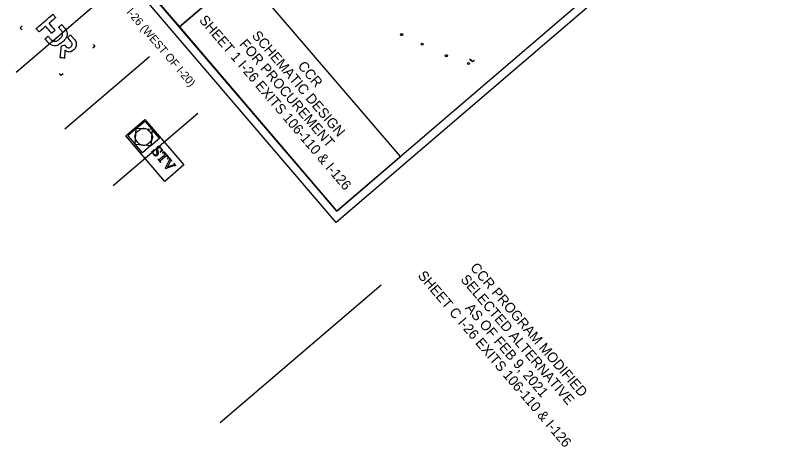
# Model space of a CAD drawing. Extents: x 1941897 to 1978064, y 805467 to 836604.
# Drawn here: x 1956688 to 1966166, y 805467 to 810856 of the extents above; entities that cross this region are included whole.
import ezdxf

# ---------------------------------------------------------------- set-up
doc = ezdxf.new("R2010")
doc.units = 0
for name, color, linetype in [('RD_EX_BldgApp', 7, 'Continuous'), ('RD_EX_BldgApp_TX', 7, 'Continuous'), ('RD_EX_DV_TX_Prop', 7, 'Continuous'), ('RD_EX_Misc', 7, 'Continuous'), ('RD_EX_RW_TxCode', 7, 'Continuous'), ('RD_EX_TX_RW_ELEV', 7, 'Continuous'), ('RD_EX_VEG', 7, 'Continuous'), ('RD_PD_Final_LnLine', 7, 'Continuous'), ('RD_SHT_Bndy', 7, 'Continuous'), ('RD_SHT_IplotShp', 7, 'Continuous'), ('RD_SHT_Misc2', 7, 'Continuous'), ('RD_SHT_Misc4', 7, 'Continuous'), ('RD_SHT_ShtClip', 7, 'Continuous'), ('RD_SHT_TX', 7, 'Continuous')]:
    doc.layers.add(name, color=color, linetype=linetype)

msp = doc.modelspace()

# ---------------------------------------------------------------- linework, layer by layer
at = {"layer": 'RD_EX_BldgApp'}
for p, q in [((1962402.7, 810274.8), (1962407.6, 810285.5)), ((1962409.9, 810284.2), (1962405.1, 810273.8))]:
    msp.add_line(p, q, dxfattribs=at)
for points in [[(1962404.9, 810275.2), (1962405.3, 810275.7), (1962405.4, 810276.2), (1962405.2, 810276.7), (1962404.8, 810277.1), (1962404.2, 810277.1), (1962403.7, 810276.9), (1962403.4, 810276.4), (1962403.4, 810275.8), (1962403.8, 810275.3), (1962404.3, 810275.1), (1962404.8, 810275.2), (1962404.9, 810275.2)], [(1962404.8, 810275.4), (1962405.2, 810275.8), (1962405.2, 810276.3), (1962404.9, 810276.7), (1962404.5, 810276.9), (1962404, 810276.8), (1962403.7, 810276.4), (1962403.6, 810275.9), (1962403.9, 810275.5), (1962404.3, 810275.3), (1962404.8, 810275.4)], [(1962404.7, 810275.6), (1962405, 810275.9), (1962405, 810276.4), (1962404.7, 810276.7), (1962404.2, 810276.7), (1962403.9, 810276.4), (1962403.8, 810276), (1962404, 810275.6), (1962404.4, 810275.5), (1962404.7, 810275.6)], [(1962404.6, 810275.8), (1962404.8, 810276.1), (1962404.7, 810276.4), (1962404.4, 810276.5), (1962404.1, 810276.4), (1962404, 810276), (1962404.2, 810275.7), (1962404.6, 810275.8), (1962404.6, 810275.8)], [(1962404.5, 810275.9), (1962404.6, 810276.2), (1962404.4, 810276.3), (1962404.2, 810276.2), (1962404.3, 810276), (1962404.5, 810275.9)], [(1962407.9, 810281.5), (1962408.3, 810281.9), (1962408.4, 810282.5), (1962408.2, 810283), (1962407.7, 810283.3), (1962407.2, 810283.4), (1962406.7, 810283.1), (1962406.4, 810282.6), (1962406.4, 810282.1), (1962406.7, 810281.6), (1962407.2, 810281.4), (1962407.8, 810281.5), (1962407.9, 810281.5)], [(1962407.8, 810281.7), (1962408.1, 810282.1), (1962408.2, 810282.6), (1962407.9, 810283), (1962407.4, 810283.2), (1962407, 810283.1), (1962406.6, 810282.7), (1962406.6, 810282.2), (1962406.8, 810281.8), (1962407.3, 810281.6), (1962407.8, 810281.7)], [(1962407.7, 810281.9), (1962407.9, 810282.2), (1962407.9, 810282.6), (1962407.6, 810282.9), (1962407.2, 810283), (1962406.8, 810282.7), (1962406.8, 810282.3), (1962407, 810281.9), (1962407.4, 810281.8), (1962407.7, 810281.9)], [(1962407.6, 810282), (1962407.8, 810282.3), (1962407.7, 810282.7), (1962407.3, 810282.8), (1962407, 810282.6), (1962407, 810282.3), (1962407.2, 810282), (1962407.5, 810282), (1962407.6, 810282)], [(1962407.5, 810282.2), (1962407.6, 810282.4), (1962407.4, 810282.6), (1962407.2, 810282.5), (1962407.2, 810282.2), (1962407.5, 810282.2)]]:
    msp.add_lwpolyline(points, dxfattribs=at)
at = {"layer": 'RD_EX_DV_TX_Prop'}
for centre, radius in [((1961516.9, 810613.9), 13.8), ((1961772.4, 810493.9), 13.7), ((1962075.3, 810349.3), 13.3), ((1962351.4, 810252.8), 13.7)]:
    msp.add_circle(centre, radius, dxfattribs=at)
at = {"layer": 'RD_EX_Misc'}
for p, q in [((1962422.9, 810289.4), (1962416.1, 810287.3)), ((1962420.5, 810285), (1962418.4, 810291.7)), ((1962418.4, 810291.7), (1962422.9, 810289.4))]:
    msp.add_line(p, q, dxfattribs=at)
for points in [[(1962367, 810300.8), (1962367.9, 810302.6), (1962366.1, 810303.5), (1962365.2, 810301.8), (1962367, 810300.8)], [(1962366.3, 810301.6), (1962366.1, 810301.7), (1962366, 810301.9), (1962366, 810302), (1962365.9, 810302.1), (1962365.9, 810302.3), (1962366, 810302.4), (1962366.1, 810302.6), (1962366.2, 810302.7), (1962366.3, 810302.7), (1962366.5, 810302.8), (1962366.6, 810302.8), (1962366.8, 810302.7), (1962366.8, 810302.7)], [(1962366.8, 810302.7), (1962366.9, 810302.6), (1962367, 810302.5), (1962367.1, 810302.4), (1962367.1, 810302.2), (1962367.1, 810302.1), (1962367.1, 810301.9), (1962367, 810301.8), (1962366.9, 810301.7), (1962366.7, 810301.6), (1962366.6, 810301.6), (1962366.4, 810301.6), (1962366.3, 810301.6), (1962366.3, 810301.6)], [(1962366.5, 810302.1), (1962366.4, 810302.1), (1962366.4, 810302.2), (1962366.5, 810302.3), (1962366.5, 810302.3), (1962366.6, 810302.3)], [(1962366.6, 810302.3), (1962366.6, 810302.2), (1962366.6, 810302.2), (1962366.6, 810302.1), (1962366.5, 810302.1), (1962366.5, 810302.1)], [(1962396.9, 810278.6), (1962397.8, 810280.4), (1962396, 810281.3), (1962395.1, 810279.6), (1962396.9, 810278.6)], [(1962396.2, 810279.4), (1962396, 810279.5), (1962395.9, 810279.7), (1962395.9, 810279.8), (1962395.8, 810279.9), (1962395.9, 810280.1), (1962395.9, 810280.2), (1962396, 810280.4), (1962396.1, 810280.5), (1962396.2, 810280.5), (1962396.4, 810280.6), (1962396.5, 810280.6), (1962396.7, 810280.5), (1962396.7, 810280.5)], [(1962396.7, 810280.5), (1962396.8, 810280.4), (1962396.9, 810280.3), (1962397, 810280.2), (1962397, 810280), (1962397, 810279.9), (1962397, 810279.7), (1962396.9, 810279.6), (1962396.8, 810279.5), (1962396.6, 810279.4), (1962396.5, 810279.4), (1962396.3, 810279.4), (1962396.2, 810279.4), (1962396.2, 810279.4)], [(1962396.4, 810279.9), (1962396.3, 810279.9), (1962396.3, 810280), (1962396.4, 810280.1), (1962396.4, 810280.1), (1962396.5, 810280.1)], [(1962396.5, 810280.1), (1962396.5, 810280), (1962396.5, 810280), (1962396.5, 810279.9), (1962396.5, 810279.9), (1962396.4, 810279.9)]]:
    msp.add_lwpolyline(points, dxfattribs=at)
msp.add_lwpolyline([(1962420.5, 810285), (1962416.1, 810287.3), (1962418.4, 810291.7), (1962422.9, 810289.4)], close=True, dxfattribs=at)
msp.add_circle((1962419.5, 810288.3), 0.15, dxfattribs=at)
at = {"layer": 'RD_EX_VEG'}
for centre in [(1962375.4, 810300.4), (1962382.5, 810293.9), (1962389.6, 810287.8)]:
    msp.add_circle(centre, 0.25, dxfattribs=at)
for centre, radius, start, end in [((1962373.7, 810300.5), 1.08, 97.42481, 267.20454), ((1962374.4, 810302.1), 0.995, 11.21113, 214.49527), ((1962374.8, 810298.9), 1.26, 158.90031, 357.18253), ((1962376.5, 810301.9), 1.22, 319.0152, 160.55315), ((1962377, 810299.9), 1.32, 229.33118, 68.20745), ((1962380.8, 810293.9), 1.08, 97.42481, 267.20454), ((1962381.5, 810295.6), 0.995, 11.21113, 214.49527), ((1962381.9, 810292.4), 1.26, 158.90031, 357.18253), ((1962383.6, 810295.4), 1.22, 319.0152, 160.55315), ((1962384, 810293.3), 1.32, 229.33118, 68.20745), ((1962387.9, 810287.9), 1.08, 97.42481, 267.20454), ((1962388.6, 810289.6), 0.995, 11.21113, 214.49527), ((1962389, 810286.4), 1.26, 158.90031, 357.18253), ((1962390.7, 810289.3), 1.22, 319.0152, 160.55315), ((1962391.2, 810287.3), 1.32, 229.33118, 68.20745)]:
    msp.add_arc(centre, radius, start, end, dxfattribs=at)
at = {"layer": 'RD_PD_Final_LnLine'}
msp.add_line((1961258.5, 807485.5), (1959248.4, 805764.6), dxfattribs=at)
at = {"layer": 'RD_SHT_Bndy'}
for points in [[(1960707.9, 808409.5), (1943668.8, 828312), (1948986.3, 832864.4), (1966025.3, 812961.9)], [(1957696.5, 811926.9), (1958739.3, 810708.9), (1959534.1, 811389.4), (1958491.3, 812607.4)], [(1958739.3, 810708.9), (1960707.9, 808409.5), (1961502.7, 809090), (1959534.1, 811389.4)]]:
    msp.add_lwpolyline(points, close=True, dxfattribs=at)
at = {"layer": 'RD_SHT_IplotShp'}
msp.add_lwpolyline([(1960696.9, 808268.5), (1943527.9, 828323), (1948997.3, 833005.4), (1966166.3, 812950.9)], close=True, dxfattribs=at)
at = {"layer": 'RD_SHT_Misc2'}
for points in [[(1956773.4, 810673.3), (1956751.4, 810699), (1956777, 810720.9)], [(1957662.8, 810489.7), (1957684.7, 810464.1), (1957659.1, 810442.1)], [(1957287.8, 810124.3), (1957262.2, 810102.3), (1957240.2, 810128)]]:
    msp.add_lwpolyline(points, dxfattribs=at)
for points in [[(1957186.8, 810665.7), (1957186.8, 810665.7), (1957111.7, 810753.5), (1957111.7, 810753.5), (1957111.7, 810753.5), (1957111.7, 810753.5), (1957195.1, 810824.9), (1957195.1, 810824.9), (1957195.1, 810824.9), (1957195.1, 810824.9), (1957158.9, 810867.1), (1957158.9, 810867.1), (1957158.9, 810867.1), (1957158.9, 810867.1), (1956950.4, 810688.6), (1956950.4, 810688.6), (1956950.4, 810688.6), (1956950.4, 810688.6), (1956986.6, 810646.3), (1956986.6, 810646.3), (1956986.6, 810646.3), (1956986.6, 810646.3), (1957070, 810717.8), (1957070, 810717.8), (1957070, 810717.8), (1957070, 810717.8), (1957145.1, 810630), (1957145.1, 810630), (1957145.1, 810630), (1957145.1, 810630), (1957186.8, 810665.7), (1957186.8, 810665.7)], [(1957275.5, 810520.1), (1957275.5, 810520.1), (1957275.6, 810520.2), (1957275.6, 810520.2), (1957275.6, 810520.2), (1957275.6, 810520.2), (1957275.6, 810520.2), (1957275.6, 810520.2), (1957275.6, 810520.2), (1957335.8, 810572), (1957342, 810653.2), (1957290.4, 810713.6), (1957290.4, 810713.6), (1957290.4, 810713.6), (1957269.3, 810738.2), (1957269.3, 810738.2), (1957269.3, 810738.2), (1957269.3, 810738.2), (1957230.1, 810704.7), (1957230.1, 810704.7), (1957230.1, 810704.7), (1957230.1, 810704.7), (1957251.2, 810680.1), (1957251.2, 810680.1), (1957251.2, 810680.1), (1957284, 810641.7), (1957280.2, 810592.1), (1957242, 810559.2), (1957242, 810559.2), (1957203.7, 810526.6), (1957153.8, 810530.2), (1957121, 810568.6), (1957121, 810568.6), (1957121, 810568.6), (1957099.9, 810593.2), (1957099.9, 810593.2), (1957099.9, 810593.2), (1957099.9, 810593.2), (1957060.7, 810559.7), (1957060.7, 810559.7), (1957060.7, 810559.7), (1957060.7, 810559.7), (1957081.8, 810535), (1957081.8, 810535), (1957081.8, 810535), (1957133.5, 810474.7), (1957215, 810468.5), (1957275.4, 810520), (1957275.4, 810520), (1957275.4, 810520), (1957275.4, 810520), (1957275.4, 810520), (1957275.4, 810520), (1957275.4, 810520), (1957275.5, 810520.1), (1957275.5, 810520.1)], [(1957342.1, 810577.2), (1957342.1, 810577.2), (1957382.4, 810530.1), (1957382.4, 810530.1), (1957382.4, 810530.1), (1957394.6, 810515.9), (1957399.8, 810503.8), (1957399, 810491), (1957399, 810491), (1957398.1, 810479.3), (1957392.8, 810469), (1957383.5, 810461.1), (1957383.5, 810461.1), (1957362.4, 810443.1), (1957334.3, 810450.5), (1957317, 810470.8), (1957317, 810470.8), (1957317, 810470.8), (1957306.9, 810482.5), (1957306.9, 810482.5), (1957306.9, 810482.5), (1957306.9, 810482.5), (1957265.3, 810470.8), (1957265.3, 810470.8), (1957265.3, 810470.8), (1957265.3, 810470.8), (1957251.4, 810325.4), (1957251.4, 810325.4), (1957251.4, 810325.4), (1957251.4, 810325.4), (1957302.2, 810317), (1957302.2, 810317), (1957302.2, 810317), (1957302.2, 810317), (1957310.5, 810418.8), (1957310.5, 810418.8), (1957310.5, 810418.8), (1957342, 810393.4), (1957387.1, 810396.4), (1957416.2, 810421.3), (1957416.2, 810421.3), (1957437.9, 810439.9), (1957449.4, 810460.4), (1957450.7, 810488.4), (1957450.7, 810488.4), (1957452.1, 810517.4), (1957440.4, 810538.3), (1957417.4, 810565.2), (1957417.4, 810565.2), (1957417.4, 810565.2), (1957379.6, 810609.3), (1957379.6, 810609.3), (1957379.6, 810609.3), (1957379.6, 810609.3), (1957342.1, 810577.2), (1957342.1, 810577.2)]]:
    msp.add_open_spline(points, degree=3, dxfattribs=at)
at = {"layer": 'RD_SHT_Misc4'}
for points in [[(1958308.3, 809555.4), (1958796.1, 808985.7), (1958557, 808781), (1958069.3, 809350.8)], [(1958532, 809173.5), (1958530.3, 809175.5), (1958524.2, 809173.3), (1958520.5, 809175.3), (1958517.7, 809182.4), (1958513.6, 809192.9), (1958508.1, 809201.4), (1958502.7, 809206.8), (1958497, 809210.7), (1958490.8, 809213.5), (1958484.1, 809214.9), (1958477.6, 809215.1), (1958471.4, 809214), (1958465.8, 809211.8), (1958460.7, 809208.2), (1958455.8, 809202.8), (1958452.6, 809196.6), (1958450.9, 809189.5), (1958450.7, 809181.5), (1958454.7, 809155.5), (1958458.5, 809133.6), (1958456.8, 809122.3), (1958451.3, 809114.4), (1958444.3, 809110.6), (1958436.1, 809109.9), (1958427.6, 809112.8), (1958420, 809119.3), (1958414.8, 809127.1), (1958411.8, 809135.6), (1958410.9, 809144.2), (1958412.2, 809151.9), (1958416.2, 809159.9), (1958423.2, 809169.5), (1958421.5, 809171.4), (1958391.2, 809145.3), (1958392.7, 809143.5), (1958398.6, 809146), (1958402, 809144.3), (1958406.7, 809133.9), (1958411.3, 809123), (1958417.2, 809115), (1958422.8, 809109.3), (1958428.8, 809105.2), (1958435.3, 809102.2), (1958442.3, 809100.8), (1958449.2, 809100.7), (1958455.6, 809101.8), (1958461.6, 809104.3), (1958467, 809108), (1958471.8, 809113.2), (1958475.3, 809119.4), (1958477.5, 809126.3), (1958478.1, 809133.7), (1958473.9, 809160.2), (1958470.7, 809179.7), (1958470.8, 809192.1), (1958472.6, 809197.4), (1958476.2, 809201.7), (1958482.5, 809205.1), (1958490.2, 809205.6), (1958497.9, 809203.2), (1958504.6, 809197.7), (1958509, 809190.9), (1958511.8, 809182.8), (1958512.4, 809174.4), (1958510.8, 809166.3), (1958506.7, 809158.2), (1958499.8, 809149.4), (1958501.5, 809147.5)], [(1958609.9, 809078.5), (1958548, 809150.9), (1958527, 809136.2), (1958529.2, 809133.7), (1958535.5, 809137.4), (1958541.4, 809139.2), (1958546.7, 809139.1), (1958551.2, 809137.6), (1958559.5, 809129.6), (1958568.5, 809119.1), (1958496.3, 809057.1), (1958489.7, 809052.2), (1958485.2, 809050.3), (1958479.7, 809051.4), (1958474.4, 809055.7), (1958471.6, 809059.1), (1958469.7, 809057.5), (1958503.9, 809017.5), (1958505.8, 809019.1), (1958503, 809022.4), (1958499.6, 809027.8), (1958498.8, 809032.9), (1958501.3, 809037.5), (1958507.7, 809043.9), (1958579.9, 809105.8), (1958591.2, 809092.8), (1958595, 809087.2), (1958597.2, 809082), (1958597.5, 809076.9), (1958596.2, 809071.5), (1958589.9, 809062.6), (1958592.2, 809060.1)], [(1958696.4, 808977.6), (1958672.7, 809005.2), (1958670.9, 809003.6), (1958671.6, 809002.3), (1958674, 808997.5), (1958674.7, 808993.5), (1958672.7, 808988.4), (1958659.2, 808982.4), (1958589.6, 808957.3), (1958622.4, 809026.7), (1958630.2, 809038.6), (1958632.7, 809040.1), (1958635.8, 809040.2), (1958639.6, 809038.4), (1958644.9, 809033.9), (1958646.8, 809035.5), (1958614.4, 809073.3), (1958612.5, 809071.6), (1958616.5, 809063.7), (1958616.5, 809056.6), (1958611.7, 809046.1), (1958563.4, 808944.1), (1958566.4, 808940.6), (1958668.6, 808977.3), (1958677.5, 808979.8), (1958684.8, 808980.3), (1958689.5, 808979), (1958694.5, 808975.9)]]:
    msp.add_lwpolyline(points, close=True, dxfattribs=at)
for points in [[(1958201, 809442), (1958307.7, 809533.3), (1958399.2, 809426.4), (1958201, 809442)], [(1958200.8, 809441.8), (1958094.1, 809350.4), (1958185.6, 809243.5), (1958200.8, 809441.8)], [(1958384.1, 809228), (1958490.9, 809319.4), (1958399.3, 809426.3), (1958384.1, 809228)], [(1958384, 809227.9), (1958277.2, 809136.5), (1958185.7, 809243.4), (1958384, 809227.9)]]:
    msp.add_lwpolyline(points, dxfattribs=at)
msp.add_open_spline([(1958215.2, 809268.8), (1958251.7, 809226.1), (1958316, 809221.1), (1958358.7, 809257.7), (1958401.4, 809294.3), (1958406.4, 809358.6), (1958369.8, 809401.3), (1958333.3, 809444), (1958269, 809449), (1958226.3, 809412.4), (1958183.6, 809375.8), (1958178.6, 809311.6), (1958215.2, 809268.8)], degree=3, dxfattribs=at)
at = {"layer": 'RD_SHT_ShtClip'}
for p, q in [((1957759.5, 811045), (1956702.2, 810139.9)), ((1958365.4, 810337.2), (1957308.2, 809432.1)), ((1958971.4, 809629.4), (1957914.2, 808724.3))]:
    msp.add_line(p, q, dxfattribs=at)

# ---------------------------------------------------------------- texts
at = {"layer": 'RD_EX_BldgApp_TX'}
msp.add_text('SIGN', height=4, rotation=62.44852, dxfattribs=at).set_placement((1962403.4, 810282.8))
at = {"layer": 'RD_EX_DV_TX_Prop'}
for s, rotation, p in [('504', 323.59367, (1961507.6, 810615.8)), ('502', 311.77146, (1961763.7, 810497.7)), ('501', 311.77146, (1962066.9, 810352.7)), ('499', 311.77146, (1962342.7, 810256.6))]:
    msp.add_text(s, height=8, rotation=rotation, dxfattribs=at).set_placement(p)
at = {"layer": 'RD_EX_RW_TxCode'}
for s, p in [('10026', (1962417.7, 810287.1)), ('RWM', (1962420.6, 810286.2))]:
    msp.add_text(s, height=1, rotation=62.44852, dxfattribs=at).set_placement(p)
at = {"layer": 'RD_EX_TX_RW_ELEV'}
msp.add_text('327.26', height=1.5, rotation=62.44852, dxfattribs=at).set_placement((1962420.6, 810288.9))
at = {"layer": 'RD_SHT_TX'}
for s, height, p in [('I-26 (WEST OF I-20)', 100, (1958072.6, 810890.8)), ('SHEET 1 I-26 EXITS 106-110 & I-126', 125, (1958979.5, 810789.8)), ('SCHEMATIC DESIGN', 125, (1959638.2, 810597.1)), ('FOR PROCUREMENT', 125, (1959482.8, 810490.3)), ('CCR', 125, (1960210.3, 810217.2)), ('CCR PROGRAM MODIFIED', 125, (1962365.9, 807699.3)), ('SHEET C I-26 EXITS 106-110 & I-126', 125, (1961710.5, 807599.9)), ('SELECTED ALTERNATIVE', 125, (1962244.8, 807552.4)), ('AS OF FEB 9, 2021', 125, (1962304.1, 807194.9))]:
    msp.add_text(s, height=height, rotation=310.56753, dxfattribs=at).set_placement(p)

doc.saveas('drawing.dxf')
